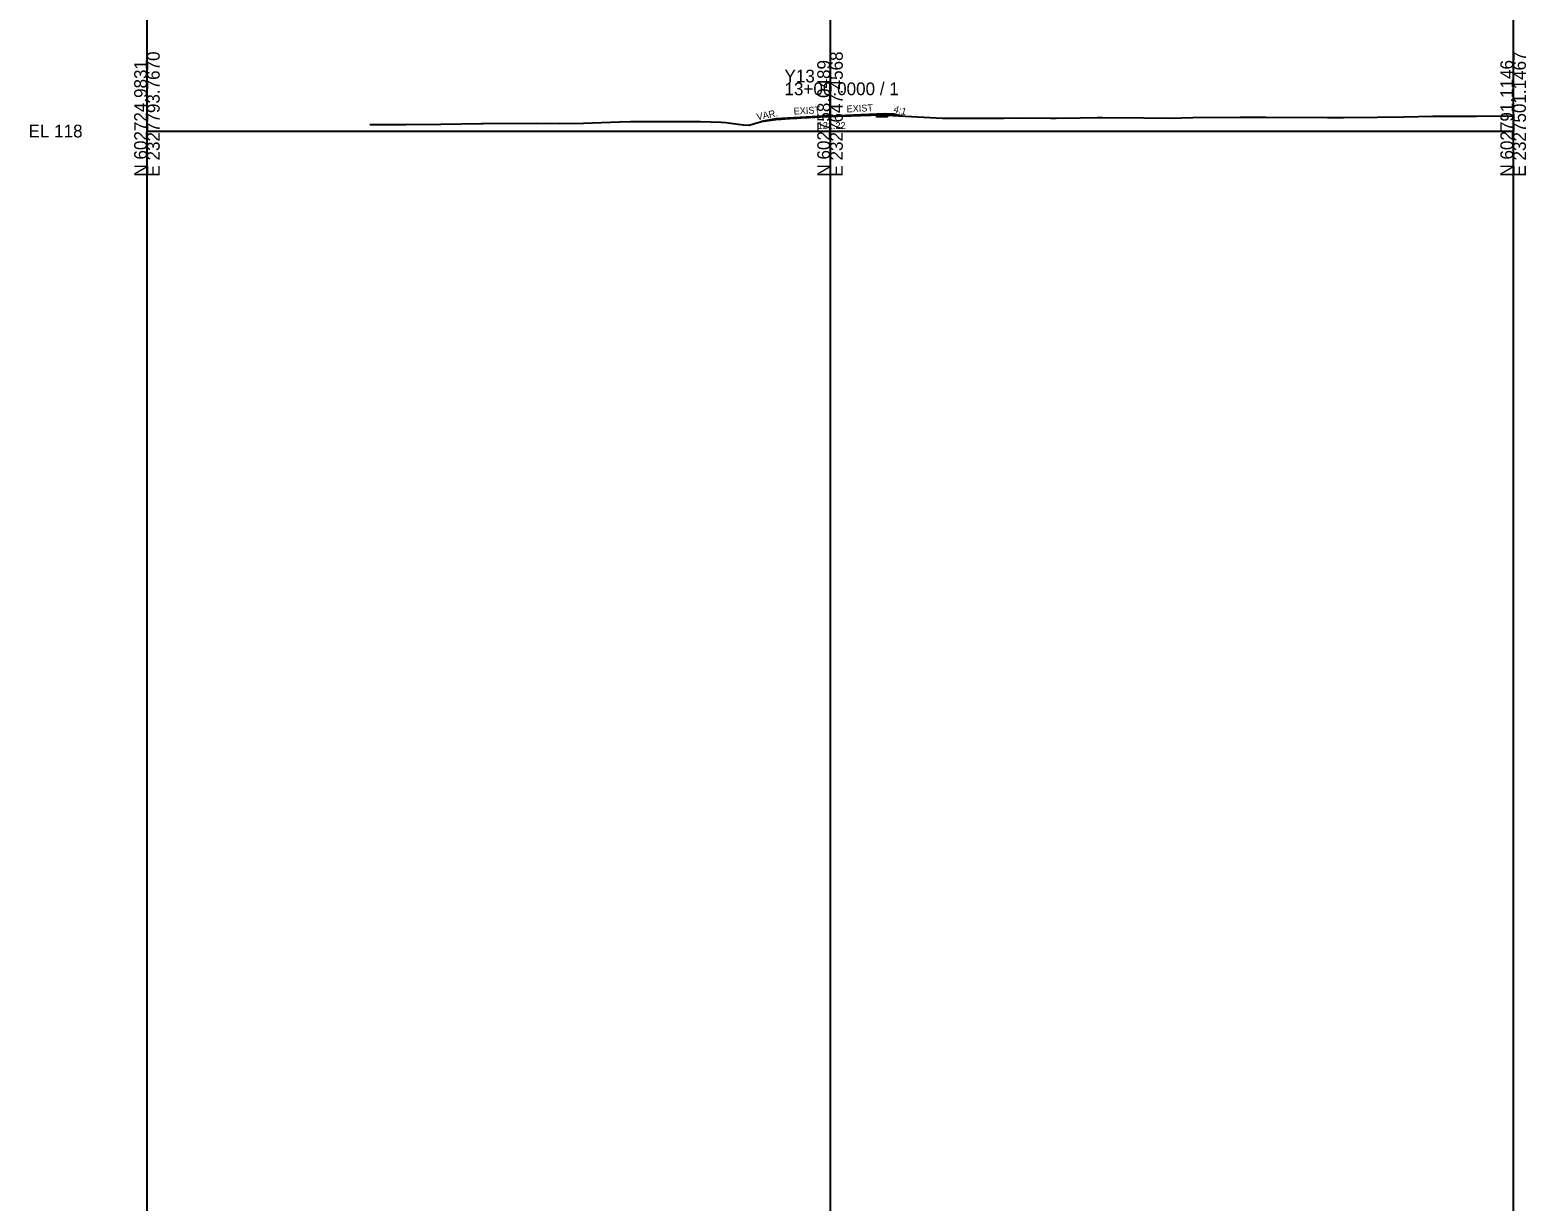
# Model space of a CAD drawing. Extents: x -26 to 1603, y -711 to 1241.
# Drawn here: x -25.7 to 302.8, y 265 to 522.2 of the extents above; entities that cross this region are included whole.
import ezdxf

# ---------------------------------------------------------------- set-up
doc = ezdxf.new("R2010")
doc.units = 0
for name, color, linetype in [('Exist CMT Pavement', 7, 'Continuous'), ('Exist Cross Section Cell', 7, 'Continuous'), ('Exist XS Center Line Elevation Label', 7, 'Continuous'), ('Exist XS Ground Line', 7, 'Continuous'), ('Prop CMT Pvmt Course 1', 7, 'Continuous'), ('Prop CMT Pvmt Course 1 Wedge', 7, 'Continuous'), ('Prop CMT Pvmt Course 2', 7, 'Continuous'), ('Prop CMT Pvmt Course 3', 7, 'Continuous'), ('Prop CMT Pvmt Surface', 7, 'Continuous'), ('Prop CMT Pvmt Surface Shoulder', 7, 'Continuous'), ('Prop CMT Pvmt Wedge Surface 1', 7, 'Continuous'), ('Prop CMT Pvmt Wedge Surface 2', 7, 'Continuous'), ('Prop CMT Pvmt Wedge Surface 3', 7, 'Continuous'), ('Prop CMT Shld Paved Course 1', 7, 'Continuous'), ('Prop CMT Shld Paved Course 2', 7, 'Continuous'), ('Prop CMT Shld Paved Course 3', 7, 'Continuous'), ('Prop CMT Slope Grass', 7, 'Continuous'), ('Prop CMT Subgrade Earthwork', 7, 'Continuous'), ('Prop XS Earthwork Shape', 7, 'Continuous'), ('Prop XS SE Text', 7, 'Continuous'), ('Prop XS Side Slope Text', 7, 'Continuous'), ('Scratch_Level_0', 7, 'Continuous'), ('Scratch_Level_1', 7, 'Continuous'), ('Scratch_Level_9', 7, 'Continuous')]:
    doc.layers.add(name, color=color, linetype=linetype)

msp = doc.modelspace()

# ---------------------------------------------------------------- linework, layer by layer
at = {"layer": 'Exist CMT Pavement'}
msp.add_lwpolyline([(138.07, 502.55), (138.43, 502.58), (138.82, 502.63), (139.23, 502.65), (140.09, 502.7), (142.3, 502.83), (142.7, 502.86), (144.62, 502.96), (145.31, 503), (146.63, 503.06), (147.92, 503.13), (148.8, 503.18), (149.5, 503.21), (150, 503.22), (150.65, 503.24), (151.06, 503.26), (153.14, 503.32), (154.67, 503.38), (155.74, 503.42), (156.68, 503.44), (158.35, 503.49), (158.99, 503.51), (160.27, 503.54)], dxfattribs=at)
at = {"layer": 'Exist Cross Section Cell'}
for p, q in [((150, 500), (150, 510.68)), ((0, 500), (150, 500)), ((150, 500), (300, 500))]:
    msp.add_line(p, q, dxfattribs=at)
at = {"layer": 'Exist XS Ground Line'}
msp.add_lwpolyline([(48.93, 501.43), (49.44, 501.44), (56.42, 501.42), (56.84, 501.43), (64.53, 501.54), (73.39, 501.67), (73.93, 501.66), (85.64, 501.7), (90.54, 501.69), (95.89, 501.76), (103.79, 502.01), (106.15, 502.09), (107.64, 502.13), (121.57, 502.09), (126.1, 501.96), (127.15, 501.89), (130.91, 501.38), (132.27, 501.29), (133.18, 501.56), (134.98, 502.09), (136.95, 502.42), (138.07, 502.55), (138.43, 502.58), (138.82, 502.63), (139.23, 502.65), (140.09, 502.7), (142.3, 502.83), (142.7, 502.86), (144.62, 502.96), (145.31, 503), (146.63, 503.06), (147.92, 503.13), (148.8, 503.18), (149.5, 503.21), (150, 503.22), (150.65, 503.24), (151.06, 503.26), (153.14, 503.32), (154.67, 503.38), (155.74, 503.42), (156.68, 503.44), (158.35, 503.49), (158.99, 503.51), (160.27, 503.54), (161.03, 503.55), (161.56, 503.56), (162.43, 503.51), (174.67, 502.87), (175.76, 502.85), (183.27, 502.84), (188.17, 502.86), (191.27, 502.88), (198.43, 502.81), (199.63, 502.82), (204.96, 502.94), (208.68, 503.01), (209.77, 502.98), (218.94, 502.92), (224.72, 502.85), (229.66, 502.97), (240.08, 503.02), (241.32, 503.04), (241.9, 503.02), (245.7, 503.02), (259.27, 502.97), (262.76, 503), (270.2, 503.09), (276, 503.14), (282.38, 503.24), (283.23, 503.25), (291.96, 503.29), (300, 503.32)], dxfattribs=at)
at = {"layer": 'Prop CMT Pvmt Course 1'}
for points in [[(150, 503.35), (138.07, 502.72)], [(150, 503.35), (160.27, 503.76)], [(160.27, 503.64), (150.01, 503.22)], [(160.27, 503.51), (160.27, 503.76)], [(160.27, 503.54), (160.27, 503.51)]]:
    msp.add_lwpolyline(points, dxfattribs=at)
at = {"layer": 'Prop CMT Pvmt Course 1 Wedge'}
msp.add_lwpolyline([(150.01, 503.22), (160.27, 503.64)], dxfattribs=at)
at = {"layer": 'Prop CMT Pvmt Course 2'}
for points in [[(160.27, 503.64), (160.27, 503.64)], [(160.27, 503.51), (160.27, 503.51)]]:
    msp.add_lwpolyline(points, dxfattribs=at)
at = {"layer": 'Prop CMT Pvmt Course 3'}
msp.add_lwpolyline([(160.27, 503.51), (160.27, 503.09)], dxfattribs=at)
at = {"layer": 'Prop CMT Pvmt Surface'}
for points in [[(150, 503.35), (138.07, 502.72)], [(150, 503.35), (160.27, 503.76)]]:
    msp.add_lwpolyline(points, dxfattribs=at)
at = {"layer": 'Prop CMT Pvmt Surface Shoulder'}
msp.add_lwpolyline([(160.27, 503.76), (162, 503.83)], dxfattribs=at)
at = {"layer": 'Prop CMT Pvmt Wedge Surface 1'}
for points in [[(150.01, 503.22), (160.27, 503.64)], [(160.27, 503.76), (160.27, 503.64)], [(160.27, 503.51), (160.27, 503.54)]]:
    msp.add_lwpolyline(points, dxfattribs=at)
at = {"layer": 'Prop CMT Pvmt Wedge Surface 2'}
msp.add_lwpolyline([(160.27, 503.51), (160.27, 503.54)], dxfattribs=at)
at = {"layer": 'Prop CMT Pvmt Wedge Surface 3'}
msp.add_lwpolyline([(160.27, 503.51), (160.27, 503.54)], dxfattribs=at)
at = {"layer": 'Prop CMT Shld Paved Course 1'}
for points in [[(160.27, 503.76), (162, 503.83), (162.24, 503.59)], [(162.24, 503.59), (160.27, 503.51)], [(160.27, 503.51), (160.27, 503.54)]]:
    msp.add_lwpolyline(points, dxfattribs=at)
at = {"layer": 'Prop CMT Shld Paved Course 2'}
for points in [[(160.27, 503.51), (162.24, 503.59)], [(162.24, 503.59), (160.27, 503.51)], [(160.27, 503.51), (160.27, 503.51)], [(162.24, 503.59), (162.24, 503.59)]]:
    msp.add_lwpolyline(points, dxfattribs=at)
at = {"layer": 'Prop CMT Shld Paved Course 3'}
for points in [[(160.27, 503.51), (162.24, 503.59)], [(160.27, 503.09), (160.27, 503.51)], [(162, 503.17), (160.27, 503.1)], [(162.24, 503.59), (162.24, 503.59)], [(162.24, 503.59), (162.64, 503.19)]]:
    msp.add_lwpolyline(points, dxfattribs=at)
at = {"layer": 'Prop CMT Slope Grass'}
for p, q in [((138.07, 502.72), (134.98, 502.09)), ((162, 503.83), (164, 503.79)), ((164, 503.79), (165.85, 503.33))]:
    msp.add_line(p, q, dxfattribs=at)
at = {"layer": 'Prop CMT Subgrade Earthwork'}
for p, q in [((160.27, 503.1), (160.27, 503.54)), ((134.98, 502.09), (138.07, 502.55))]:
    msp.add_line(p, q, dxfattribs=at)
for points in [[(160.27, 503.1), (162.64, 503.19)], [(162.64, 503.19), (163.26, 503.81)]]:
    msp.add_lwpolyline(points, dxfattribs=at)
at = {"layer": 'Prop XS Earthwork Shape'}
for points in [[(160.27, 503.1), (160.27, 503.54), (161.03, 503.55), (161.56, 503.56), (162.43, 503.51), (162.94, 503.48), (162.64, 503.19)], [(164, 503.79), (165.85, 503.33), (162.94, 503.48), (163.26, 503.81)], [(134.98, 502.09), (136.95, 502.42), (138.07, 502.55)]]:
    msp.add_lwpolyline(points, close=True, dxfattribs=at)
at = {"layer": 'Scratch_Level_1'}
msp.add_line((150, 503.35), (160.27, 503.76), dxfattribs=at)
at = {"layer": 'Scratch_Level_9'}
for p, q in [((0, 1241.32), (0, -711.39)), ((150, 1241.32), (150, -711.39)), ((300, 1241.32), (300, -711.39))]:
    msp.add_line(p, q, dxfattribs=at)

# ---------------------------------------------------------------- texts
at = {"layer": 'Exist Cross Section Cell'}
for s, p in [('E 2327793.7670', (2.8, 490)), ('E 2327647.4568', (152.8, 490)), ('E 2327501.1467', (302.8, 490)), ('N 602724.9831', (0, 490)), ('N 602758.0489', (150, 490)), ('N 602791.1146', (300, 490))]:
    msp.add_text(s, height=2.8, rotation=90, dxfattribs=at).set_placement(p)
for s, p in [('Y13', (140, 510.68)), ('13+00.0000 / 1', (140, 507.88)), ('EL 118', (-26, 498.6))]:
    msp.add_text(s, height=2.8, dxfattribs=at).set_placement(p)
at = {"layer": 'Exist XS Center Line Elevation Label'}
msp.add_text('121.22', height=1.5, dxfattribs=at).set_placement((147.29, 500.47))
at = {"layer": 'Prop XS SE Text'}
for p in [(142.05, 503.61), (153.67, 504.09)]:
    msp.add_text('EXIST', height=1.5, rotation=3.0314, dxfattribs=at).set_placement(p)
at = {"layer": 'Prop XS Side Slope Text'}
for s, rotation, p in [('VAR.', 11.383, (134.05, 502.37)), ('4:1', 345.9638, (163.86, 504.16))]:
    msp.add_text(s, height=1.5, rotation=rotation, dxfattribs=at).set_placement(p)
at = {"layer": 'Scratch_Level_0'}
for s, p in [('RT_PV1_OEEOP', (160.17, 503.75)), ('RT_PV3_OEEOP', (160.16, 503.63)), ('RT_Sub_OEOT', (160.17, 503.08)), ('RT_PV1_OEOT', (160.18, 503.75)), ('RT_PV3_OEOT', (160.17, 503.5)), ('RT_PV2_OEOT', (160.17, 503.5)), ('RT_PS1_OEOP', (161.93, 503.85)), ('RT_PS3_Shelf_Out', (162.1, 503.58)), ('RT_PS3_OEOP', (162.14, 503.58)), ('RT_PS2_OEOP', (162.14, 503.58)), ('RT_Sub_Trench_Out', (162.49, 503.18)), ('RT_Sub_Trench_Out_DLT', (163.05, 503.78))]:
    msp.add_text(s, height=0.02, dxfattribs=at).set_placement(p)

doc.saveas('drawing.dxf')
